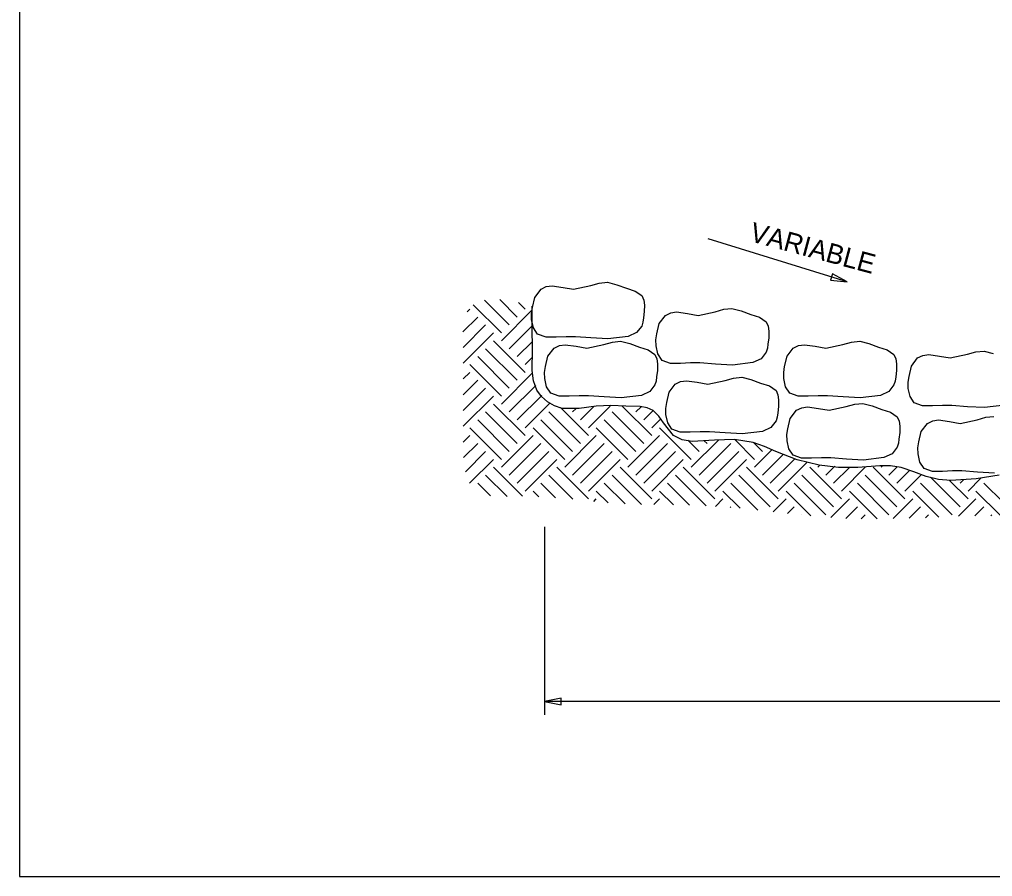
# Model space of a CAD drawing. Extents: x -439.1 to -407.9, y -458.1 to -436.2.
# Drawn here: x -439.11 to -431.65, y -458.05 to -451.48 of the extents above; entities that cross this region are included whole.
import ezdxf

# ---------------------------------------------------------------- set-up
doc = ezdxf.new("R2010")
doc.units = 0
doc.layers.add('Draft_Named_Boundary', color=7, linetype='Continuous')
doc.layers.add('Level 4', color=7, linetype='Continuous')

msp = doc.modelspace()

# ---------------------------------------------------------------- linework, layer by layer
at = {"layer": 'Draft_Named_Boundary'}
msp.add_lwpolyline([(-439.109, -458.0508), (-407.859, -458.0508), (-407.859, -437.6758), (-439.109, -437.6758)], close=True, dxfattribs=at)
at = {"layer": 'Level 4'}
for p, q in [((-432.7661, -453.4922), (-433.8317, -453.161)), ((-435.4156, -453.8828), (-435.631, -453.6673)), ((-435.3549, -453.8222), (-435.5459, -453.6312)), ((-435.2943, -453.7615), (-435.428, -453.6279)), ((-435.2337, -453.7009), (-435.2847, -453.6499)), ((-435.7108, -453.8749), (-435.5974, -453.7615)), ((-435.6774, -453.7203), (-435.658, -453.7009)), ((-435.4156, -453.9434), (-435.1812, -453.709)), ((-435.7091, -453.9944), (-435.5368, -453.8222)), ((-435.3549, -454.004), (-435.1804, -453.8295)), ((-435.7078, -454.1144), (-435.4762, -453.8828)), ((-435.2337, -454.1858), (-435.4762, -453.9434)), ((-435.2943, -454.0646), (-435.1779, -453.9482)), ((-435.3549, -454.3071), (-435.5974, -454.0646)), ((-435.2943, -454.2465), (-435.5368, -454.004)), ((-435.4156, -454.3677), (-435.658, -454.1252)), ((-435.2337, -454.1252), (-435.1789, -454.0704)), ((-435.7078, -454.2356), (-435.658, -454.1858)), ((-435.4156, -454.4283), (-435.1763, -454.189)), ((-435.7078, -454.3568), (-435.5974, -454.2465)), ((-435.3549, -454.4889), (-435.152, -454.286)), ((-435.7078, -454.4781), (-435.5368, -454.3071)), ((-435.7078, -454.5993), (-435.4762, -454.3677)), ((-435.2943, -454.5495), (-435.1066, -454.3618)), ((-435.2337, -454.6708), (-435.4762, -454.4283)), ((-435.2337, -454.6101), (-435.0431, -454.4195)), ((-435.2943, -454.7314), (-435.5368, -454.4889)), ((-434.8094, -454.7314), (-435.0519, -454.4889)), ((-434.7488, -454.6708), (-434.9639, -454.4556)), ((-434.87, -454.4889), (-434.8439, -454.4628)), ((-434.8094, -454.5495), (-434.7064, -454.4465)), ((-434.7488, -454.6101), (-434.5827, -454.444)), ((-434.3245, -454.7314), (-434.567, -454.4889)), ((-434.2639, -454.6708), (-434.4906, -454.444)), ((-434.3851, -454.4889), (-434.3458, -454.4496)), ((-434.3245, -454.5495), (-434.2538, -454.4788)), ((-435.3549, -454.792), (-435.5974, -454.5495)), ((-434.87, -454.792), (-435.1125, -454.5495)), ((-434.3851, -454.792), (-434.6276, -454.5495)), ((-434.2639, -454.6101), (-434.1947, -454.541)), ((-435.4156, -454.8526), (-435.658, -454.6101)), ((-434.9306, -454.8526), (-435.1731, -454.6101)), ((-434.4457, -454.8526), (-434.6882, -454.6101)), ((-433.9608, -454.8526), (-434.2033, -454.6101)), ((-435.7078, -454.7205), (-435.658, -454.6708)), ((-435.7054, -454.8394), (-435.5974, -454.7314)), ((-435.4156, -454.9132), (-435.1731, -454.6708)), ((-435.3549, -454.9738), (-435.1125, -454.7314)), ((-434.9306, -454.9132), (-434.6882, -454.6708)), ((-434.87, -454.9738), (-434.6276, -454.7314)), ((-434.4457, -454.9132), (-434.2033, -454.6708)), ((-434.3851, -454.9738), (-434.1427, -454.7314)), ((-433.9002, -454.792), (-433.9878, -454.7044)), ((-433.9608, -454.9132), (-433.7524, -454.7048)), ((-433.9002, -454.9738), (-433.6578, -454.7314)), ((-433.8396, -454.7314), (-433.8609, -454.7101)), ((-433.4759, -454.8526), (-433.6271, -454.7015)), ((-433.4153, -454.792), (-433.483, -454.7243)), ((-435.6919, -454.9471), (-435.5368, -454.792)), ((-435.2943, -455.0344), (-435.0519, -454.792)), ((-434.8094, -455.0344), (-434.567, -454.792)), ((-434.3245, -455.0344), (-434.0821, -454.792)), ((-433.8396, -455.0344), (-433.5971, -454.792)), ((-433.4759, -454.9132), (-433.343, -454.7803)), ((-433.4153, -454.9738), (-433.2556, -454.8141)), ((-435.6596, -455.0361), (-435.4762, -454.8526)), ((-435.2337, -455.0951), (-434.9913, -454.8526)), ((-434.7488, -455.0951), (-434.5064, -454.8526)), ((-434.2639, -455.0951), (-434.0214, -454.8526)), ((-433.779, -455.0951), (-433.5365, -454.8526)), ((-433.3547, -455.0344), (-433.1677, -454.8474)), ((-433.2941, -455.0951), (-433.073, -454.874)), ((-435.2552, -455.1342), (-435.4762, -454.9132)), ((-434.7488, -455.1557), (-434.9913, -454.9132)), ((-434.2639, -455.1557), (-434.5064, -454.9132)), ((-433.779, -455.1557), (-434.0214, -454.9132)), ((-433.2941, -455.1557), (-433.5365, -454.9132)), ((-432.8092, -455.1557), (-433.0516, -454.9132)), ((-432.991, -454.9132), (-432.9756, -454.8978)), ((-432.9304, -454.9738), (-432.8611, -454.9046)), ((-432.8698, -455.0344), (-432.7466, -454.9113)), ((-432.8092, -455.0951), (-432.6249, -454.9108)), ((-432.3242, -455.1557), (-432.5667, -454.9132)), ((-432.5061, -454.9132), (-432.4972, -454.9044)), ((-432.4455, -454.9738), (-432.3843, -454.9126)), ((-432.3849, -455.0344), (-432.2865, -454.936)), ((-435.4998, -455.1321), (-435.5974, -455.0344)), ((-435.3727, -455.1379), (-435.5368, -454.9738)), ((-434.9998, -455.1471), (-435.1125, -455.0344)), ((-434.8681, -455.1576), (-435.0519, -454.9738)), ((-434.4677, -455.1944), (-434.6276, -455.0344)), ((-434.3428, -455.198), (-434.567, -454.9738)), ((-433.9729, -455.2042), (-434.1427, -455.0344)), ((-433.8472, -455.2087), (-434.0821, -454.9738)), ((-433.4511, -455.2411), (-433.6578, -455.0344)), ((-433.3547, -455.2163), (-433.5971, -454.9738)), ((-432.9304, -455.2769), (-433.1728, -455.0344)), ((-432.8698, -455.2163), (-433.1122, -454.9738)), ((-432.4455, -455.2769), (-432.6879, -455.0344)), ((-432.3849, -455.2163), (-432.6273, -454.9738)), ((-432.3242, -455.0951), (-432.1994, -454.9702)), ((-431.9606, -455.2769), (-432.203, -455.0344)), ((-431.8999, -455.2163), (-432.126, -454.9903)), ((-431.8393, -455.1557), (-431.9816, -455.0134)), ((-431.8999, -455.0344), (-431.8742, -455.0086)), ((-431.8393, -455.0951), (-431.7409, -454.9966)), ((-431.569, -455.1836), (-431.7181, -455.0344)), ((-435.1275, -455.1407), (-435.1731, -455.0951)), ((-434.5969, -455.1864), (-434.6882, -455.0951)), ((-434.0964, -455.202), (-434.2033, -455.0951)), ((-433.5857, -455.2277), (-433.7184, -455.0951)), ((-433.0431, -455.2854), (-433.2335, -455.0951)), ((-432.5358, -455.3078), (-432.7485, -455.0951)), ((-432.0631, -455.2956), (-432.2636, -455.0951)), ((-431.5897, -455.284), (-431.7787, -455.0951)), ((-434.708, -455.1755), (-434.6882, -455.1557)), ((-434.2474, -455.1998), (-434.2033, -455.1557)), ((-433.7757, -455.213), (-433.7184, -455.1557)), ((-433.3321, -455.2543), (-433.2335, -455.1557)), ((-432.8918, -455.2989), (-432.7485, -455.1557)), ((-432.4142, -455.3062), (-432.2636, -455.1557)), ((-431.9119, -455.2889), (-431.7787, -455.1557)), ((-433.6624, -455.2209), (-433.6578, -455.2163)), ((-433.2229, -455.2664), (-433.1728, -455.2163)), ((-432.7771, -455.3054), (-432.6879, -455.2163)), ((-432.2913, -455.3046), (-432.203, -455.2163)), ((-431.7865, -455.2846), (-431.7181, -455.2163)), ((-433.1136, -455.2783), (-433.1122, -455.2769)), ((-432.6598, -455.3094), (-432.6273, -455.2769)), ((-432.1656, -455.3001), (-432.1424, -455.2769)), ((-431.6649, -455.2843), (-431.6575, -455.2769)), ((-435.0842, -455.3705), (-435.0842, -456.8116)), ((-421.7848, -456.7088), (-435.0842, -456.7088))]:
    msp.add_line(p, q, dxfattribs=at)
for points in [[(-432.8946, -453.4797), (-432.7661, -453.4922), (-432.879, -453.4295)], [(-432.8946, -453.4797), (-432.7661, -453.4922), (-432.879, -453.4295)], [(-435.1774, -453.6891), (-435.159, -453.6105), (-435.1117, -453.5479), (-435.0713, -453.5283), (-435.0263, -453.5216), (-434.9435, -453.5339), (-434.862, -453.5479), (-434.7307, -453.5199), (-434.6657, -453.5011), (-434.6024, -453.4953), (-434.5318, -453.5133), (-434.4578, -453.5413), (-434.3907, -453.5622), (-434.3395, -453.5971), (-434.3251, -453.6308), (-434.3198, -453.6694), (-434.3208, -453.719), (-434.3264, -453.768), (-434.3311, -453.8002), (-434.3395, -453.8304), (-434.3794, -453.8803), (-434.4429, -453.9104), (-434.5991, -453.929), (-434.7291, -453.9218), (-434.8488, -453.9126), (-434.9205, -453.9127), (-434.9967, -453.9159), (-435.0738, -453.9159), (-435.138, -453.8929), (-435.1702, -453.8439), (-435.184, -453.7811), (-435.1848, -453.7342), (-435.1774, -453.6891)], [(-434.2238, -453.8899), (-434.2054, -453.8113), (-434.158, -453.7486), (-434.1177, -453.7291), (-434.0726, -453.7223), (-433.9898, -453.7347), (-433.9083, -453.7486), (-433.777, -453.7207), (-433.712, -453.7019), (-433.6487, -453.696), (-433.5781, -453.7141), (-433.5042, -453.742), (-433.437, -453.7629), (-433.3859, -453.7979), (-433.3715, -453.8315), (-433.3661, -453.8702), (-433.3671, -453.9198), (-433.3727, -453.9688), (-433.3775, -454.001), (-433.3859, -454.0312), (-433.4258, -454.0811), (-433.4893, -454.1112), (-433.6454, -454.1298), (-433.7754, -454.1225), (-433.8952, -454.1133), (-433.9669, -454.1134), (-434.043, -454.1166), (-434.1201, -454.1166), (-434.1843, -454.0936), (-434.2165, -454.0447), (-434.2303, -453.9819), (-434.2311, -453.935), (-434.2238, -453.8899)], [(-435.077, -454.1409), (-435.0587, -454.0623), (-435.0113, -453.9996), (-434.9709, -453.98), (-434.9259, -453.9733), (-434.8431, -453.9856), (-434.7616, -453.9996), (-434.6303, -453.9717), (-434.5653, -453.9529), (-434.502, -453.947), (-434.4314, -453.965), (-434.3574, -453.993), (-434.2903, -454.0139), (-434.2391, -454.0489), (-434.2247, -454.0825), (-434.2194, -454.1212), (-434.2204, -454.1708), (-434.226, -454.2197), (-434.2308, -454.2519), (-434.2391, -454.2822), (-434.2791, -454.3321), (-434.3425, -454.3621), (-434.4987, -454.3807), (-434.6287, -454.3735), (-434.7484, -454.3643), (-434.8201, -454.3644), (-434.8963, -454.3676), (-434.9734, -454.3676), (-435.0376, -454.3446), (-435.0698, -454.2956), (-435.0836, -454.2329), (-435.0844, -454.186), (-435.077, -454.1409)], [(-433.245, -454.1409), (-433.2267, -454.0623), (-433.1793, -453.9996), (-433.1389, -453.98), (-433.0939, -453.9733), (-433.0111, -453.9856), (-432.9296, -453.9996), (-432.7983, -453.9717), (-432.7333, -453.9529), (-432.67, -453.947), (-432.5994, -453.965), (-432.5254, -453.993), (-432.4583, -454.0139), (-432.4071, -454.0489), (-432.3927, -454.0825), (-432.3874, -454.1212), (-432.3884, -454.1708), (-432.394, -454.2197), (-432.3988, -454.2519), (-432.4071, -454.2822), (-432.4471, -454.3321), (-432.5105, -454.3621), (-432.6667, -454.3807), (-432.7967, -454.3735), (-432.9164, -454.3643), (-432.9881, -454.3644), (-433.0643, -454.3676), (-433.1414, -454.3676), (-433.2056, -454.3446), (-433.2378, -454.2956), (-433.2516, -454.2329), (-433.2524, -454.186), (-433.245, -454.1409)], [(-434.1485, -454.4169), (-434.1301, -454.3383), (-434.0828, -454.2756), (-434.0424, -454.2561), (-433.9973, -454.2493), (-433.9145, -454.2617), (-433.833, -454.2756), (-433.7017, -454.2477), (-433.6367, -454.2289), (-433.5735, -454.2231), (-433.5029, -454.2411), (-433.4289, -454.2691), (-433.3617, -454.2899), (-433.3106, -454.3249), (-433.2962, -454.3585), (-433.2909, -454.3972), (-433.2919, -454.4468), (-433.2974, -454.4958), (-433.3022, -454.528), (-433.3106, -454.5582), (-433.3505, -454.6081), (-433.414, -454.6382), (-433.5702, -454.6568), (-433.7001, -454.6496), (-433.8199, -454.6404), (-433.8916, -454.6405), (-433.9678, -454.6436), (-434.0449, -454.6436), (-434.109, -454.6206), (-434.1413, -454.5717), (-434.155, -454.5089), (-434.1558, -454.462), (-434.1485, -454.4169)], [(-433.2199, -454.6177), (-433.2016, -454.5391), (-433.1542, -454.4764), (-433.1138, -454.4569), (-433.0688, -454.4501), (-432.986, -454.4625), (-432.9045, -454.4764), (-432.7732, -454.4485), (-432.7082, -454.4297), (-432.6449, -454.4238), (-432.5743, -454.4419), (-432.5003, -454.4698), (-432.4332, -454.4907), (-432.382, -454.5257), (-432.3676, -454.5593), (-432.3623, -454.598), (-432.3633, -454.6476), (-432.3689, -454.6966), (-432.3737, -454.7288), (-432.382, -454.759), (-432.422, -454.8089), (-432.4854, -454.8389), (-432.6416, -454.8576), (-432.7716, -454.8503), (-432.8913, -454.8411), (-432.963, -454.8412), (-433.0392, -454.8444), (-433.1163, -454.8444), (-433.1805, -454.8214), (-433.2127, -454.7724), (-433.2265, -454.7097), (-433.2273, -454.6628), (-433.2199, -454.6177)], [(-434.9578, -456.6825), (-435.0842, -456.7088), (-434.9578, -456.735)]]:
    msp.add_lwpolyline(points, close=True, dxfattribs=at)
for points in [[(-435.0618, -454.4109), (-435.1077, -454.3701), (-435.143, -454.3219), (-435.1704, -454.2499), (-435.1806, -454.1717), (-435.1779, -454.008), (-435.1802, -453.842), (-435.1808, -453.6786)], [(-431.5569, -454.4374), (-431.7131, -454.456), (-431.843, -454.4488), (-431.9628, -454.4396), (-432.0345, -454.4397), (-432.1107, -454.4429), (-432.1878, -454.4429), (-432.2519, -454.4199), (-432.2842, -454.3709), (-432.2979, -454.3082), (-432.2987, -454.2613), (-432.2914, -454.2162), (-432.2914, -454.2162), (-432.273, -454.1375), (-432.2257, -454.0749), (-432.1853, -454.0553), (-432.1402, -454.0486), (-432.0574, -454.0609), (-431.9759, -454.0749), (-431.8446, -454.047), (-431.7796, -454.0281), (-431.7163, -454.0223), (-431.6458, -454.0403)], [(-431.6008, -454.9746), (-431.7765, -455.0022), (-431.9712, -455.0151), (-432.067, -455.0066), (-432.1603, -454.9848), (-432.2561, -454.948), (-432.3521, -454.915), (-432.4327, -454.9033), (-432.5154, -454.903), (-432.6836, -454.915), (-432.8331, -454.9149), (-432.9801, -454.8975), (-433.148, -454.8549), (-433.3115, -454.7929), (-433.3984, -454.7549), (-433.4859, -454.7231), (-433.6292, -454.7011), (-433.7825, -454.7057), (-433.953, -454.7152), (-434.0308, -454.704), (-434.0964, -454.6708), (-434.1733, -454.5727), (-434.21, -454.5204), (-434.2534, -454.4789), (-434.2991, -454.4579), (-434.3511, -454.4479), (-434.4627, -454.444), (-434.5778, -454.4408), (-434.6895, -454.444), (-434.8204, -454.463), (-434.9511, -454.4615), (-435.0085, -454.4421), (-435.0618, -454.4109)], [(-431.6378, -454.9579), (-431.7677, -454.9507), (-431.8875, -454.9415), (-431.9592, -454.9416), (-432.0354, -454.9448), (-432.1125, -454.9448), (-432.1767, -454.9218), (-432.2089, -454.8728), (-432.2227, -454.8101), (-432.2235, -454.7632), (-432.2161, -454.7181), (-432.2161, -454.7181), (-432.1977, -454.6395), (-432.1504, -454.5768), (-432.11, -454.5572), (-432.0649, -454.5505), (-431.9821, -454.5628), (-431.9006, -454.5768), (-431.7693, -454.5489), (-431.7043, -454.5301), (-431.6411, -454.5242)]]:
    msp.add_lwpolyline(points, dxfattribs=at)

# ---------------------------------------------------------------- texts
msp.add_text('VARIABLE', height=0.15, rotation=345, dxfattribs=at).set_placement((-433.5215, -453.1777))

doc.saveas('drawing.dxf')
